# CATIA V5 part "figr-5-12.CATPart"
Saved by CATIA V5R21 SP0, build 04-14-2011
Part number: Part1
Bounding box of the stored display mesh (mm): x 0 to 150, y -70 to 70, z -150 to 69.804
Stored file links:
  D:\CATIA V5R21 E-RESOURCES\CATIA-V5R21\catia-v5r21-prt\c05-catia-v5r20-prt\catia-v5r21-figr-5-12.CATPart
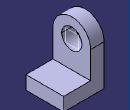
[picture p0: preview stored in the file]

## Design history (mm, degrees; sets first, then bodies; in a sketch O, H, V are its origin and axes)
Set1
  Plane1: type 1Curve, Element1 edge [face of Pad1 | face of Pad1]
Body1 (main body)
  Sketch1 on yz-plane, origin (0, 0, 0), H (0, 1, 0), V (0, 0, 1)
    arc A1 centre (0, 0) radius 70 from (70, 0) to (-70, 0) ccw
    point P1 (70, 0)
    point P2 (-70, 0)
    line L1 (-70, 0) -> (-70, -150)
    line L2 (-70, -150) -> (70, -150)
    line L3 (70, -150) -> (70, 0)
    circle A2 centre (0, 0) radius 37.5
    radius A1 = 70
    radius A2 = 37.5
    distance O L2 = 150
    coincidence: P1 H, P2 H
    tangency: L1 A1, L3 A1
    horizontal: L2 H
  Pad1: profile Sketch1, direction (1, 0, 0), length 50
  Sketch2 on face of Pad1, origin (50, 0, 0), H (0, 1, 0), V (0, 0, 1)
    line L1 (-70, -150) -> (70, -150)
    line L2 (70, -150) -> (70, -100)
    line L3 (70, -100) -> (-70, -100)
    line L4 (-70, -100) -> (-70, -150)
    reference projected line E1 (-70, -150) -> (70, -150) from edge [face of Pad1 | face of Pad1]
    reference projected line E2 (-70, 0) -> (-70, -150) from edge [face of Pad1 | face of Pad1]
    reference projected line E3 (70, -150) -> (70, 0) from edge [face of Pad1 | face of Pad1]
    length L2 = 50
    horizontal: L1 H, L3 H
    vertical: L2 V, L4 V
    coincidence: L1 E1, E2 L4, L2 E3
  Pad2: profile Sketch2, direction (1, 0, 0), length 100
